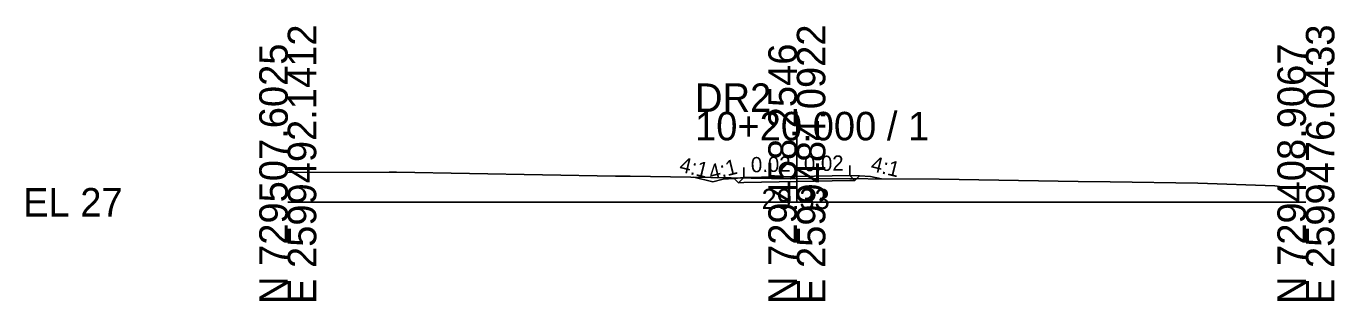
# Model space of a CAD drawing. Extents: x -26 to 1162, y -10 to 9515.
# Drawn here: x -25.7 to 102.8, y 990.3 to 1017.3 of the extents above; entities that cross this region are included whole.
import ezdxf

# ---------------------------------------------------------------- set-up
doc = ezdxf.new("R2010")
doc.units = 0
for name, color, linetype in [('Exist Cross Section Cell', 7, 'Continuous'), ('Exist XS Center Line Elevation Label', 7, 'Continuous'), ('Exist XS Ground Line', 7, 'Continuous'), ('Prop XS Ditch Slope Text', 7, 'Continuous'), ('Prop XS Dump Level', 7, 'Continuous'), ('Prop XS EOT Tick Mark', 7, 'Continuous'), ('Prop XS Finish Grade', 7, 'Continuous'), ('Prop XS Finish Grade Earthwork', 7, 'Continuous'), ('Prop XS Finish Grade Pavement', 7, 'Continuous'), ('Prop XS Pvmt Edge Slope', 7, 'Continuous'), ('Prop XS SE Text', 7, 'Continuous'), ('Prop XS Side Slope Text', 7, 'Continuous'), ('Prop XS Subgrade Earthwork', 7, 'Continuous')]:
    doc.layers.add(name, color=color, linetype=linetype)

msp = doc.modelspace()

# ---------------------------------------------------------------- linework, layer by layer
at = {"layer": 'Exist Cross Section Cell'}
for p, q in [((50, 1000), (50, 1008.89)), ((0, 1000), (50, 1000)), ((50, 1000), (100, 1000))]:
    msp.add_line(p, q, dxfattribs=at)
at = {"layer": 'Exist XS Ground Line'}
msp.add_lwpolyline([(0, 1002.92), (9.96, 1002.96), (10.68, 1002.96), (32.18, 1002.58), (33.62, 1002.57), (47.51, 1002.34), (50, 1002.33), (63.98, 1002.27), (77.63, 1002.05), (80.77, 1002), (89.37, 1001.87), (96.96, 1001.61), (97.39, 1001.54), (100, 1001.44)], dxfattribs=at)
at = {"layer": 'Prop XS Dump Level'}
for p, q in [((55.2, 1002.63), (50, 1002.53)), ((50, 1002.53), (44.8, 1002.43))]:
    msp.add_line(p, q, dxfattribs=at)
at = {"layer": 'Prop XS EOT Tick Mark'}
for p, q in [((44.8, 1002.43), (44.8, 1003.43)), ((55.2, 1002.63), (55.2, 1003.63))]:
    msp.add_line(p, q, dxfattribs=at)
at = {"layer": 'Prop XS Finish Grade'}
for p, q in [((55.2, 1002.63), (56.16, 1002.6)), ((44.8, 1002.43), (43.83, 1002.35))]:
    msp.add_line(p, q, dxfattribs=at)
at = {"layer": 'Prop XS Finish Grade Earthwork'}
for p, q in [((56.16, 1002.6), (57.24, 1002.55)), ((41.74, 1002.02), (39.89, 1002.47)), ((42.76, 1002.27), (41.74, 1002.02)), ((43.83, 1002.35), (42.76, 1002.27)), ((57.24, 1002.55), (58.3, 1002.29))]:
    msp.add_line(p, q, dxfattribs=at)
at = {"layer": 'Prop XS Finish Grade Pavement'}
for p, q in [((50, 1002.53), (55.2, 1002.63)), ((44.8, 1002.43), (50, 1002.53))]:
    msp.add_line(p, q, dxfattribs=at)
at = {"layer": 'Prop XS Pvmt Edge Slope'}
for p, q in [((55.2, 1002.63), (55.7, 1002.14)), ((55.7, 1002.14), (56.16, 1002.6)), ((44.28, 1001.92), (43.83, 1002.35)), ((44.8, 1002.43), (44.28, 1001.92))]:
    msp.add_line(p, q, dxfattribs=at)
at = {"layer": 'Prop XS Subgrade Earthwork'}
for p, q in [((55.7, 1002.14), (56.16, 1002.6)), ((44.28, 1001.92), (43.83, 1002.35)), ((44.8, 1001.93), (44.28, 1001.92)), ((50, 1002.03), (44.8, 1001.93)), ((55.2, 1002.13), (50, 1002.03)), ((55.2, 1002.13), (55.7, 1002.14))]:
    msp.add_line(p, q, dxfattribs=at)

# ---------------------------------------------------------------- texts
at = {"layer": 'Exist Cross Section Cell'}
for s, p in [('E 2599492.1412', (2.8, 990)), ('E 2599484.0922', (52.8, 990)), ('E 2599476.0433', (102.8, 990)), ('N 729507.6025', (0, 990)), ('N 729458.2546', (50, 990)), ('N 729408.9067', (100, 990))]:
    msp.add_text(s, height=2.8, rotation=90, dxfattribs=at).set_placement(p)
for s, p in [('DR2', (40, 1008.89)), ('10+20.000 / 1', (40, 1006.09)), ('EL 27', (-26, 998.6))]:
    msp.add_text(s, height=2.8, dxfattribs=at).set_placement(p)
at = {"layer": 'Exist XS Center Line Elevation Label'}
msp.add_text('29.33', height=2, dxfattribs=at).set_placement((46.54, 999.33))
at = {"layer": 'Prop XS Ditch Slope Text'}
msp.add_text('4:1', height=1.5, rotation=13.7635, dxfattribs=at).set_placement((41.56, 1002.17))
at = {"layer": 'Prop XS Dump Level'}
for p in [(57.24, 1002.51), (42.76, 1002.23)]:
    msp.add_text('Case1', height=0.04, dxfattribs=at).set_placement(p)
at = {"layer": 'Prop XS SE Text'}
for p in [(45.5, 1002.94), (50.71, 1003.04)]:
    msp.add_text('0.02', height=1.5, rotation=1.1458, dxfattribs=at).set_placement(p)
at = {"layer": 'Prop XS Side Slope Text'}
for p in [(38.37, 1003.04), (57.17, 1003.11)]:
    msp.add_text('4:1', height=1.5, rotation=346.2365, dxfattribs=at).set_placement(p)

doc.saveas('drawing.dxf')
